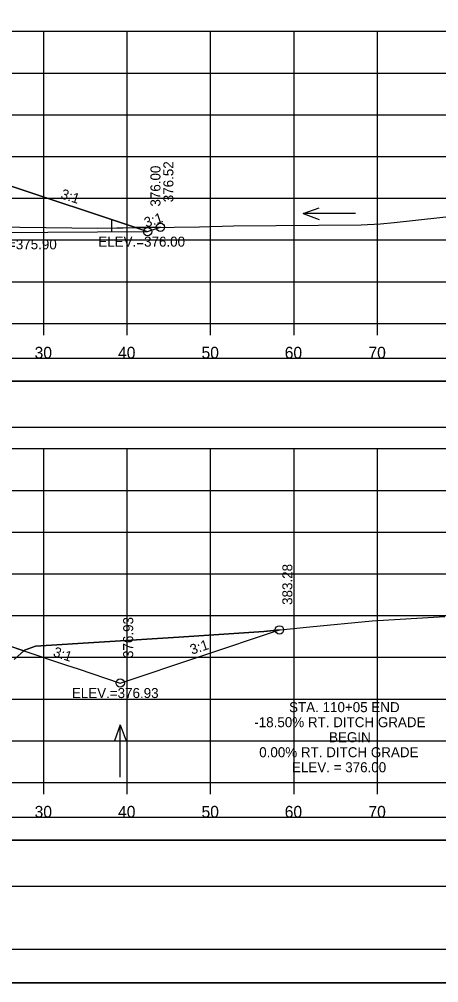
# Model space of a CAD drawing. Extents: x -37291014 to -37290680, y -936053 to -933067.
# Drawn here: x -37290816 to -37290765.8, y -934133.3 to -934017.8 of the extents above; entities that cross this region are included whole.
import ezdxf

# ---------------------------------------------------------------- set-up
doc = ezdxf.new("R2010")
doc.units = 0
for name, color, linetype in [('Default', 7, 'Continuous'), ('R_Axis', 7, 'Continuous'), ('R_Axis Annot', 7, 'Continuous'), ('R_Border', 7, 'Continuous'), ('R_Contours', 7, 'Continuous'), ('R_Exist Surface', 7, 'Continuous'), ('R_Fin Surface', 7, 'Continuous'), ('R_Grid', 7, 'Continuous'), ('R_No Plot', 7, 'Continuous'), ('R_Water', 7, 'Continuous'), ('R_Water Annot', 7, 'Continuous'), ('R_Xsect Elev', 7, 'Continuous'), ('R_Xsect Slope', 7, 'Continuous')]:
    doc.layers.add(name, color=color, linetype=linetype)

msp = doc.modelspace()

# ---------------------------------------------------------------- linework, layer by layer
at = {"layer": 'Default'}
for points in [[(-37290992.48, -934061.19), (-37290693.72, -934061.19), (-37290693.72, -934058.48), (-37290992.48, -934058.48)], [(-37290992.48, -934066.71), (-37290693.72, -934066.71), (-37290693.72, -934061.19), (-37290992.48, -934061.19)], [(-37290992.48, -934116.19), (-37290693.72, -934116.19), (-37290693.72, -934113.48), (-37290992.48, -934113.48)], [(-37290992.48, -934121.71), (-37290693.72, -934121.71), (-37290693.72, -934116.19), (-37290992.48, -934116.19)]]:
    msp.add_lwpolyline(points, close=True, dxfattribs=at)
at = {"layer": 'R_Axis'}
for p, q in [((-37290993.1, -934054.28), (-37290693.1, -934054.28)), ((-37290813.1, -934055.68), (-37290813.1, -934054.28)), ((-37290803.1, -934055.68), (-37290803.1, -934054.28)), ((-37290793.1, -934055.68), (-37290793.1, -934054.28)), ((-37290783.1, -934055.68), (-37290783.1, -934054.28)), ((-37290773.1, -934055.68), (-37290773.1, -934054.28)), ((-37290993.1, -934109.28), (-37290693.1, -934109.28)), ((-37290813.1, -934110.68), (-37290813.1, -934109.28)), ((-37290803.1, -934110.68), (-37290803.1, -934109.28)), ((-37290793.1, -934110.68), (-37290793.1, -934109.28)), ((-37290783.1, -934110.68), (-37290783.1, -934109.28)), ((-37290773.1, -934110.68), (-37290773.1, -934109.28))]:
    msp.add_line(p, q, dxfattribs=at)
at = {"layer": 'R_Border'}
msp.add_line((-37290684.92, -934129.28), (-37291001.1, -934129.28), dxfattribs=at)
at = {"layer": 'R_Contours'}
for p, q in [((-37290799.11, -934042.76), (-37290802.1, -934042.8)), ((-37290784.86, -934091), (-37290786.71, -934091.19)), ((-37290815.5, -934093.5), (-37290818.93, -934092.36))]:
    msp.add_line(p, q, dxfattribs=at)
for points in [[(-37290802.1, -934042.8), (-37290817.46, -934037.68), (-37290817.46, -934037.34), (-37290818.46, -934037.35), (-37290818.93, -934037.19)], [(-37290823.34, -934042.47), (-37290815.98, -934042.74), (-37290806.6, -934042.86), (-37290802.1, -934042.8)], [(-37290802.1, -934042.8), (-37290800.66, -934043.28), (-37290799.11, -934042.76)], [(-37290815.5, -934093.5), (-37290810.38, -934095.21), (-37290808.99, -934095.67), (-37290803.93, -934097.36), (-37290784.86, -934091)], [(-37290786.71, -934091.19), (-37290796.92, -934091.85), (-37290805.81, -934092.41), (-37290814.08, -934092.95), (-37290815.41, -934093.42), (-37290815.5, -934093.5)], [(-37290816.64, -934094.53), (-37290815.5, -934093.5)]]:
    msp.add_lwpolyline(points, dxfattribs=at)
at = {"layer": 'R_Exist Surface'}
for points in [[(-37290823.34, -934042.47), (-37290815.98, -934042.74), (-37290806.6, -934042.86), (-37290794.45, -934042.71), (-37290790.37, -934042.6), (-37290775.05, -934042.47), (-37290772.73, -934042.36), (-37290771.12, -934042.2), (-37290759.8, -934040.96)], [(-37290816.64, -934094.53), (-37290815.41, -934093.42), (-37290814.08, -934092.95), (-37290805.81, -934092.41), (-37290796.92, -934091.85), (-37290786.71, -934091.19), (-37290781.2, -934090.63), (-37290773.75, -934089.89), (-37290765.02, -934089.37)]]:
    msp.add_lwpolyline(points, dxfattribs=at)
at = {"layer": 'R_Fin Surface'}
for points in [[(-37290817.46, -934037.68), (-37290802.1, -934042.8), (-37290800.66, -934043.28), (-37290799.11, -934042.76)], [(-37290818.93, -934092.36), (-37290815.5, -934093.5), (-37290810.38, -934095.21), (-37290808.99, -934095.67), (-37290803.93, -934097.36), (-37290784.86, -934091)]]:
    msp.add_lwpolyline(points, dxfattribs=at)
at = {"layer": 'R_Grid'}
for p, q in [((-37290993.1, -934019.28), (-37290693.1, -934019.28)), ((-37290813.1, -934054.28), (-37290813.1, -934019.28)), ((-37290803.1, -934054.28), (-37290803.1, -934019.28)), ((-37290793.1, -934054.28), (-37290793.1, -934019.28)), ((-37290783.1, -934054.28), (-37290783.1, -934019.28)), ((-37290773.1, -934054.28), (-37290773.1, -934019.28)), ((-37290993.1, -934024.28), (-37290693.1, -934024.28)), ((-37290993.1, -934029.28), (-37290693.1, -934029.28)), ((-37290993.1, -934034.28), (-37290693.1, -934034.28)), ((-37290993.1, -934039.28), (-37290693.1, -934039.28)), ((-37290993.1, -934044.28), (-37290693.1, -934044.28)), ((-37290993.1, -934049.28), (-37290693.1, -934049.28)), ((-37290993.1, -934054.28), (-37290693.1, -934054.28)), ((-37290993.1, -934069.28), (-37290693.1, -934069.28)), ((-37290813.1, -934109.28), (-37290813.1, -934069.28)), ((-37290803.1, -934109.28), (-37290803.1, -934069.28)), ((-37290793.1, -934109.28), (-37290793.1, -934069.28)), ((-37290783.1, -934109.28), (-37290783.1, -934069.28)), ((-37290773.1, -934109.28), (-37290773.1, -934069.28)), ((-37290993.1, -934074.28), (-37290693.1, -934074.28)), ((-37290993.1, -934079.28), (-37290693.1, -934079.28)), ((-37290993.1, -934084.28), (-37290693.1, -934084.28)), ((-37290993.1, -934089.28), (-37290693.1, -934089.28)), ((-37290993.1, -934094.28), (-37290693.1, -934094.28)), ((-37290993.1, -934099.28), (-37290693.1, -934099.28)), ((-37290993.1, -934104.28), (-37290693.1, -934104.28)), ((-37290993.1, -934109.28), (-37290693.1, -934109.28))]:
    msp.add_line(p, q, dxfattribs=at)
at = {"layer": 'R_No Plot'}
msp.add_line((-37291013.5, -934133.26), (-37290680.17, -934133.26), dxfattribs=at)
for points in [[(-37291013.51, -933919.93), (-37290680.17, -933919.93), (-37290680.17, -934133.26), (-37291013.51, -934133.26)], [(-37290767.18, -933923.82), (-37290747.56, -933923.82), (-37290747.56, -933933.7), (-37290731.45, -933933.7), (-37290708.25, -933933.7), (-37290708.25, -933958.03), (-37290684.92, -933958.03), (-37290684.92, -934129.28), (-37291001.1, -934129.28), (-37291001.1, -933923.82)]]:
    msp.add_lwpolyline(points, close=True, dxfattribs=at)
for centre in [(-37290800.66, -934043.28), (-37290799.11, -934042.76), (-37290784.86, -934091), (-37290803.93, -934097.36)]:
    msp.add_circle(centre, 0.5, dxfattribs=at)
at = {"layer": 'R_Water'}
for p, q in [((-37290804.93, -934043.31), (-37290804.93, -934041.86)), ((-37290885.72, -934043.78), (-37290800.65, -934043.28))]:
    msp.add_line(p, q, dxfattribs=at)
at = {"layer": 'R_Water Annot'}
for p, q in [((-37290782.03, -934041.11), (-37290780.1, -934040.41)), ((-37290775.74, -934041.11), (-37290782.03, -934041.11)), ((-37290782.03, -934041.11), (-37290780.1, -934041.81)), ((-37290803.93, -934102.35), (-37290804.63, -934104.27)), ((-37290803.93, -934108.63), (-37290803.93, -934102.35)), ((-37290803.93, -934102.35), (-37290803.23, -934104.27))]:
    msp.add_line(p, q, dxfattribs=at)

# ---------------------------------------------------------------- texts
at = {"layer": 'R_Axis Annot'}
for s, p in [('30', (-37290814.19, -934058.48)), ('40', (-37290804.19, -934058.48)), ('50', (-37290794.19, -934058.48)), ('60', (-37290784.22, -934058.48)), ('70', (-37290774.19, -934058.48)), ('30', (-37290814.19, -934113.48)), ('40', (-37290804.19, -934113.48)), ('50', (-37290794.19, -934113.48)), ('60', (-37290784.22, -934113.48)), ('70', (-37290774.19, -934113.48))]:
    msp.add_text(s, height=1.4, dxfattribs=at).set_placement(p)
at = {"layer": 'R_Water Annot'}
msp.add_text('F.L. INLET=375.90', height=1.2, dxfattribs=at).set_placement((-37290825.14, -934045.4))
at = {"layer": 'R_Xsect Elev'}
for s, p in [('376.52', (-37290797.56, -934039.76)), ('376.00', (-37290799.11, -934040.28)), ('383.28', (-37290783.31, -934088)), ('376.93', (-37290802.38, -934094.36))]:
    msp.add_text(s, height=1.2, rotation=90, dxfattribs=at).set_placement(p)
for s, p in [('ELEV.=376.00', (-37290806.56, -934045.08)), ('ELEV.=376.93', (-37290809.73, -934099.16)), ('STA. 110+05 END', (-37290783.7, -934100.85)), ('-18.50% RT. DITCH GRADE', (-37290787.87, -934102.65)), ('BEGIN', (-37290778.91, -934104.45)), ('0.00% RT. DITCH GRADE', (-37290787.28, -934106.25)), ('ELEV. = 376.00', (-37290783.35, -934108.05))]:
    msp.add_text(s, height=1.2, dxfattribs=at).set_placement(p)
at = {"layer": 'R_Xsect Slope'}
for rotation, p in [(341.5668, (-37290811.15, -934039.26)), (18.4332, (-37290800.83, -934042.81)), (18.4332, (-37290795.34, -934093.97)), (341.5668, (-37290812.06, -934094.12))]:
    msp.add_text('3:1', height=1.2, rotation=rotation, dxfattribs=at).set_placement(p)

doc.saveas('drawing.dxf')
